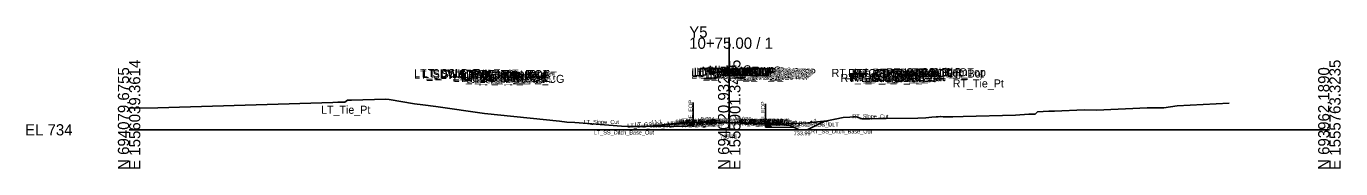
# Model space of a CAD drawing. Extents: x -26 to 4229, y -10 to 9523.
# Drawn here: x -25.7 to 302.8, y 990.3 to 1025.8 of the extents above; entities that cross this region are included whole.
import ezdxf

# ---------------------------------------------------------------- set-up
doc = ezdxf.new("R2010")
doc.units = 0
for name, color, linetype in [('Default', 7, 'Continuous'), ('Exist CMT Pavement', 7, 'Continuous'), ('Exist Cross Section Cell', 7, 'Continuous'), ('Exist XS Center Line Elevation Label', 7, 'Continuous'), ('Exist XS Ground Line', 7, 'Continuous'), ('Prop CMT Pvmt Course 1', 7, 'Continuous'), ('Prop CMT Pvmt Course 1 Wedge', 7, 'Continuous'), ('Prop CMT Pvmt Course 2', 7, 'Continuous'), ('Prop CMT Pvmt Course 2 Wedge', 7, 'Continuous'), ('Prop CMT Pvmt Course 3', 7, 'Continuous'), ('Prop CMT Pvmt Surface', 7, 'Continuous'), ('Prop CMT Pvmt Surface Shoulder', 7, 'Continuous'), ('Prop CMT Pvmt Wedge Surface 1', 7, 'Continuous'), ('Prop CMT Pvmt Wedge Surface 2', 7, 'Continuous'), ('Prop CMT Pvmt Wedge Surface 3', 7, 'Continuous'), ('Prop CMT Shld Paved Course 1', 7, 'Continuous'), ('Prop CMT Shld Paved Course 2', 7, 'Continuous'), ('Prop CMT Shld Paved Course 3', 7, 'Continuous'), ('Prop CMT Slope Grass', 7, 'Continuous'), ('Prop CMT Subgrade Earthwork', 7, 'Continuous'), ('Prop XS Earthwork Shape', 7, 'Continuous'), ('Prop XS Label Text', 7, 'Continuous'), ('Prop XSC Text', 7, 'Continuous'), ('Scratch_Level_1', 7, 'Continuous'), ('Scratch_Level_2', 7, 'Continuous')]:
    doc.layers.add(name, color=color, linetype=linetype)

msp = doc.modelspace()

# ---------------------------------------------------------------- linework, layer by layer
at = {"layer": 'Exist CMT Pavement'}
for p, q in [((142.88, 1001.8), (140.95, 1001.81)), ((157.26, 1001.51), (159.05, 1001.45))]:
    msp.add_line(p, q, dxfattribs=at)
for points in [[(142.88, 1001.8), (150, 1001.75)], [(150, 1001.75), (150.52, 1001.75), (152.93, 1001.68), (157.26, 1001.51)]]:
    msp.add_lwpolyline(points, dxfattribs=at)
at = {"layer": 'Exist Cross Section Cell'}
for p, q in [((150, 1000), (150, 1023.01)), ((0, 1000), (150, 1000)), ((150, 1000), (300, 1000))]:
    msp.add_line(p, q, dxfattribs=at)
at = {"layer": 'Exist XS Ground Line'}
msp.add_lwpolyline([(0, 1005.37), (7.19, 1005.5), (15.32, 1005.71), (50.91, 1006.82), (52.21, 1006.88), (53.27, 1006.87), (53.89, 1006.87), (54.63, 1007.36), (55.56, 1007.37), (64.15, 1007.67), (64.97, 1007.55), (71.36, 1006.51), (73.41, 1006.21), (76.71, 1005.81), (88.81, 1004.07), (107.54, 1002.15), (109.43, 1001.91), (111.39, 1001.86), (123.06, 1000.94), (124.74, 1000.82), (128.94, 1000.82), (129.37, 1000.87), (130.48, 1000.92), (136.24, 1001.61), (140.95, 1001.81), (142.85, 1001.8), (150, 1001.75), (150.52, 1001.75), (152.93, 1001.68), (159.05, 1001.45), (160.86, 1001.29), (162.67, 1001.37), (169.64, 1001.72), (174.39, 1002.24), (176.48, 1002.66), (178.44, 1003.05), (181.83, 1003.2), (182.72, 1002.88), (183.19, 1002.7), (185.16, 1002.74), (187.29, 1002.78), (189.2, 1002.8), (197.14, 1002.92), (199.18, 1003.02), (200.61, 1003.15), (201.69, 1003.21), (202.16, 1003.21), (202.88, 1003.33), (203.48, 1003.21), (204.23, 1003.21), (205.37, 1003.23), (205.88, 1003.24), (208.45, 1003.32), (221.55, 1003.64), (224.87, 1003.91), (225.22, 1003.9), (226.48, 1003.93), (227.02, 1004.46), (229.9, 1004.64), (231.31, 1004.66), (238.69, 1005.02), (241.78, 1004.91), (254.44, 1005.46), (258.66, 1005.52), (261.94, 1005.95), (274.95, 1006.62)], dxfattribs=at)
at = {"layer": 'Prop CMT Pvmt Course 1'}
for points in [[(150, 1001.8), (140.88, 1001.84)], [(140.88, 1001.84), (140.88, 1001.59)], [(140.88, 1001.59), (140.95, 1001.59)], [(140.95, 1001.59), (140.95, 1001.71)], [(150, 1001.8), (159.26, 1001.56)], [(159.05, 1001.32), (159.05, 1001.44)], [(159.26, 1001.31), (159.05, 1001.32)], [(159.26, 1001.56), (159.26, 1001.31)]]:
    msp.add_lwpolyline(points, dxfattribs=at)
at = {"layer": 'Prop CMT Pvmt Course 1 Wedge'}
msp.add_lwpolyline([(159.05, 1001.44), (159.05, 1001.32)], dxfattribs=at)
at = {"layer": 'Prop CMT Pvmt Course 2'}
for points in [[(140.95, 1001.59), (140.88, 1001.59)], [(140.88, 1001.59), (140.88, 1001.34)], [(140.88, 1001.34), (140.95, 1001.34)], [(140.95, 1001.34), (140.95, 1001.59)], [(159.05, 1001.07), (159.05, 1001.32)], [(159.05, 1001.32), (159.26, 1001.31)], [(159.05, 1001.07), (159.26, 1001.06)], [(159.26, 1001.31), (159.26, 1001.06)]]:
    msp.add_lwpolyline(points, dxfattribs=at)
at = {"layer": 'Prop CMT Pvmt Course 2 Wedge'}
for points in [[(157.26, 1001.51), (154.89, 1001.6)], [(159.05, 1001.32), (159.05, 1001.2)]]:
    msp.add_lwpolyline(points, dxfattribs=at)
at = {"layer": 'Prop CMT Pvmt Course 3'}
for points in [[(140.95, 1001.34), (140.88, 1001.34)], [(140.88, 1001.34), (140.88, 1000.96)], [(140.88, 1000.96), (140.95, 1000.96)], [(140.95, 1000.96), (140.95, 1001.34)], [(159.05, 1001.07), (159.26, 1001.06)], [(159.05, 1000.69), (159.05, 1001.07)], [(159.26, 1000.69), (159.05, 1000.69)], [(159.26, 1001.06), (159.26, 1000.69)]]:
    msp.add_lwpolyline(points, dxfattribs=at)
at = {"layer": 'Prop CMT Pvmt Surface'}
for points in [[(150, 1001.8), (140.88, 1001.84)], [(150, 1001.8), (159.26, 1001.56)]]:
    msp.add_lwpolyline(points, dxfattribs=at)
at = {"layer": 'Prop CMT Pvmt Surface Shoulder'}
for points in [[(140.88, 1001.84), (140.88, 1001.84)], [(159.26, 1001.56), (159.26, 1001.56)]]:
    msp.add_lwpolyline(points, dxfattribs=at)
at = {"layer": 'Prop CMT Pvmt Wedge Surface 1'}
for points in [[(140.88, 1001.59), (140.88, 1001.84)], [(140.95, 1001.59), (140.88, 1001.59)], [(140.95, 1001.71), (140.95, 1001.59)], [(159.05, 1001.44), (159.05, 1001.32)], [(159.05, 1001.32), (159.26, 1001.31)], [(159.26, 1001.31), (159.26, 1001.56)]]:
    msp.add_lwpolyline(points, dxfattribs=at)
at = {"layer": 'Prop CMT Pvmt Wedge Surface 2'}
for points in [[(140.88, 1001.59), (140.88, 1001.84)], [(140.95, 1001.59), (140.88, 1001.59)], [(159.05, 1001.32), (159.26, 1001.31)], [(159.26, 1001.31), (159.26, 1001.56)]]:
    msp.add_lwpolyline(points, dxfattribs=at)
at = {"layer": 'Prop CMT Pvmt Wedge Surface 3'}
for points in [[(140.88, 1001.34), (140.88, 1001.84)], [(140.95, 1001.34), (140.88, 1001.34)], [(159.05, 1001.07), (159.26, 1001.06)], [(159.26, 1001.06), (159.26, 1001.56)]]:
    msp.add_lwpolyline(points, dxfattribs=at)
at = {"layer": 'Prop CMT Shld Paved Course 1'}
for points in [[(140.88, 1001.84), (140.63, 1001.58)], [(140.63, 1001.58), (140.88, 1001.59)], [(140.88, 1001.84), (140.88, 1001.84)], [(140.88, 1001.59), (140.88, 1001.84)], [(159.26, 1001.56), (159.26, 1001.56)], [(159.26, 1001.56), (159.52, 1001.31)], [(159.26, 1001.31), (159.26, 1001.56)], [(159.52, 1001.31), (159.26, 1001.31)]]:
    msp.add_lwpolyline(points, dxfattribs=at)
at = {"layer": 'Prop CMT Shld Paved Course 2'}
for points in [[(140.88, 1001.59), (140.63, 1001.58), (140.37, 1001.33)], [(140.37, 1001.33), (140.88, 1001.34)], [(140.88, 1001.34), (140.88, 1001.59)], [(159.26, 1001.31), (159.52, 1001.31), (159.77, 1001.05)], [(159.26, 1001.06), (159.26, 1001.31)], [(159.77, 1001.05), (159.26, 1001.06)]]:
    msp.add_lwpolyline(points, dxfattribs=at)
at = {"layer": 'Prop CMT Shld Paved Course 3'}
for points in [[(140.88, 1001.34), (140.37, 1001.33), (139.87, 1001.32), (139.49, 1000.94)], [(139.49, 1000.94), (140.88, 1000.96)], [(140.88, 1000.96), (140.88, 1001.34)], [(159.26, 1001.06), (159.77, 1001.05), (160.27, 1001.04), (160.65, 1000.66)], [(159.26, 1000.69), (159.26, 1001.06)], [(160.65, 1000.66), (159.26, 1000.69)]]:
    msp.add_lwpolyline(points, dxfattribs=at)
at = {"layer": 'Prop CMT Slope Grass'}
for p, q in [((173.82, 1002.18), (169.45, 999.99)), ((165.26, 1001.08), (167.45, 999.99)), ((167.45, 999.99), (169.45, 999.99))]:
    msp.add_line(p, q, dxfattribs=at)
for points in [[(140.88, 1001.84), (134.88, 1001.36), (128.94, 1000.82)], [(159.26, 1001.56), (165.26, 1001.08)]]:
    msp.add_lwpolyline(points, dxfattribs=at)
at = {"layer": 'Prop CMT Subgrade Earthwork'}
for points in [[(139.49, 1000.94), (128.94, 1000.82)], [(140.88, 1000.96), (139.49, 1000.94)], [(140.95, 1000.96), (140.88, 1000.96)], [(140.95, 1000.96), (140.95, 1001.81)], [(159.05, 1000.69), (159.05, 1001.45)], [(159.05, 1000.69), (159.26, 1000.69)], [(159.26, 1000.69), (160.65, 1000.66)], [(160.65, 1000.66), (166.33, 1000.55)]]:
    msp.add_lwpolyline(points, dxfattribs=at)
at = {"layer": 'Prop XS Earthwork Shape'}
for points in [[(162, 1001.34), (162.67, 1001.37), (169.64, 1001.72), (173.82, 1002.18), (169.45, 999.99), (167.45, 999.99), (166.33, 1000.55), (165.26, 1001.08)], [(129.66, 1000.88), (130.48, 1000.92), (131.74, 1001.07), (134.88, 1001.36), (140.07, 1001.78), (140.95, 1001.81), (140.95, 1000.96), (140.88, 1000.96), (139.49, 1000.94), (128.94, 1000.82)], [(129.66, 1000.88), (128.94, 1000.82), (129.37, 1000.87)], [(131.74, 1001.07), (136.24, 1001.61), (140.07, 1001.78), (134.88, 1001.36)], [(140.95, 1001.81), (142.85, 1001.8), (150, 1001.75), (142.88, 1001.8)], [(157.26, 1001.51), (159.05, 1001.45), (152.93, 1001.68)], [(159.05, 1000.69), (159.05, 1001.45), (160.86, 1001.29), (162, 1001.34), (165.26, 1001.08), (166.33, 1000.55), (160.65, 1000.66), (159.26, 1000.69)]]:
    msp.add_lwpolyline(points, close=True, dxfattribs=at)
at = {"layer": 'Prop XS Label Text'}
for p, q in [((140.95, 1006.81), (140.95, 1001.81)), ((159.05, 1006.45), (159.05, 1001.45))]:
    msp.add_line(p, q, dxfattribs=at)
at = {"layer": 'Scratch_Level_2'}
msp.add_line((128.94, 1000.82), (134.88, 1001.36), dxfattribs=at)

# ---------------------------------------------------------------- texts
at = {"layer": 'Default'}
for s, height, p in [('LT_CSLP_Pnt', 2, (73.17, 1013.15)), ('LT_PV2_OEEOP', 2, (140.56, 1013.36)), ('LT_PV1_OEEOP', 2, (141.12, 1013.48)), ('LT_PV2_IEEOP', 2, (141.2, 1013.36)), ('LT_PV1_IEEOP', 2, (141.77, 1013.48)), ('LT_PV2_PGL1', 2, (142.13, 1013.36)), ('LT_PV2_PGL', 2, (142.46, 1013.36)), ('LT_PV1_PGL', 2, (143.03, 1013.61)), ('MI_Face In', 2, (143.15, 1013.77)), ('MI_Bot In', 2, (144.13, 1013.61)), ('MI_Top In', 2, (144.86, 1014.02)), ('MI_Crown', 2, (149.07, 1014.1)), ('RT_PV1_OEEOP', 2, (150.58, 1013.24)), ('MI_Face Out', 2, (151.01, 1013.53)), ('MI_Top Out', 2, (151.22, 1013.78)), ('RT_PV1_IEEOP', 2, (151.22, 1013.24)), ('MI_Bot Out', 2, (152.01, 1013.37)), ('RT_PV1_PGL', 2, (152.48, 1013.37)), ('RT_Sub_Trench_Out_DLT', 2, (175.59, 1013.19)), ('RT_CG_Top_Face', 2, (179.71, 1013.15)), ('RT_CG_Top_BOC', 2, (181.24, 1013.15)), ('RT_SDWK_In_Top', 2, (185.81, 1013.26)), ('RT_SDWK_Out_Top', 2, (189.19, 1013.36)), ('RT_Shld_O', 2, (195.54, 1013.35)), ('CSLP_Pnt', 2, (197.87, 1013.39)), ('LT_SDWK_Out_Top', 2, (71.24, 1013.12)), ('LT_SDWK_Out_Bot', 2, (71.27, 1012.79)), ('LT_Sub_Trench_Out_DLT', 2, (73.49, 1012.95)), ('LT_SDWK_In_Top', 2, (77.86, 1013.02)), ('LT_SDWK_In_Bot', 2, (77.89, 1012.69)), ('LT_CG1_Shelf_Out', 2, (81.05, 1011.89)), ('LT_CG_Top_Face', 2, (82.76, 1012.91)), ('LT_CG_Top_BOC', 2, (83.28, 1012.91)), ('LT_CG_Bot_BOC', 2, (83.31, 1011.9)), ('LT_CG_Top_Gut', 2, (83.74, 1012.41)), ('LT_Sub_OEOP', 2, (84.36, 1011.63)), ('LT_Sub_OEOT_CG', 2, (84.87, 1011.7)), ('LT_CG_Bot_IE', 2, (87.41, 1011.95)), ('LT_Sub_OEOT', 2, (87.58, 1011.66)), ('LT_PV2_OEOT', 2, (87.67, 1012.28)), ('LT_PV3_OEOT', 2, (87.67, 1012.03)), ('LT_PV1_OEOT', 2, (88.24, 1012.53)), ('LT_Sub_OEEOP', 2, (140.46, 1012.73)), ('LT_PV3_OEEOP', 2, (140.56, 1013.11)), ('LT_PV3_PGL1', 2, (142.13, 1013.11)), ('LT_PV4_PGL', 2, (142.46, 1012.73)), ('RT_Sub_OEEOP', 2, (149.92, 1012.49)), ('RT_PV2_OEEOP', 2, (150.01, 1013.12)), ('RT_PV3_OEEOP', 2, (150.01, 1012.87)), ('RT_PV2_IEEOP', 2, (150.66, 1013.12)), ('RT_PV2_PGL1', 2, (151.58, 1013.12)), ('RT_PV3_PGL1', 2, (151.58, 1012.87)), ('RT_PV2_PGL', 2, (151.92, 1013.12)), ('RT_PV4_PGL', 2, (151.92, 1012.49)), ('RT_Sub_OEOT_CG', 2, (177.82, 1011.94)), ('RT_CG1_Shelf_Out', 2, (180, 1012.13)), ('RT_CG_Bot_IE', 2, (180.37, 1012.19)), ('RT_Sub_OEOT', 2, (180.53, 1011.9)), ('RT_PV2_OEOT', 2, (180.63, 1012.52)), ('RT_PV3_OEOT', 2, (180.63, 1012.27)), ('RT_CG_Top_Gut', 2, (180.69, 1012.65)), ('RT_PV1_OEOT', 2, (181.19, 1012.77)), ('RT_CG_Bot_BOC', 2, (181.27, 1012.14)), ('RT_Sub_OEOP', 2, (183.82, 1011.87)), ('RT_SDWK_In_Bot', 2, (185.84, 1012.93)), ('RT_SDWK_Out_Bot', 2, (189.22, 1013.03)), ('RT_Tie_Pt', 2, (205.86, 1010.57)), ('LT_Tie_Pt', 2, (47.97, 1004)), ('-', 0.0001, (0, 1000)), ('-', 0.0001, (0, 1000)), ('-', 0.0001, (0, 1000)), ('-', 0.0001, (0, 1000)), ('-', 0.0001, (0, 1000)), ('-', 0.0001, (0, 1000)), ('-', 0.0001, (0, 1000)), ('-', 0.0001, (0, 1000)), ('-', 0.0001, (0, 1000)), ('-', 0.0001, (0, 1000))]:
    msp.add_text(s, height=height, dxfattribs=at).set_placement(p)
at = {"layer": 'Exist Cross Section Cell'}
for s, p in [('Y5', (140, 1023.01)), ('10+75.00 / 1', (140, 1020.21)), ('EL 734', (-26, 998.6))]:
    msp.add_text(s, height=2.8, dxfattribs=at).set_placement(p)
for s, p in [('N 694079.6755', (0, 990)), ('E 1556039.3614', (2.8, 990)), ('N 694020.9323', (150, 990)), ('E 1555901.3425', (152.8, 990)), ('N 693962.1890', (300, 990)), ('E 1555763.3235', (302.8, 990))]:
    msp.add_text(s, height=2.8, rotation=90, dxfattribs=at).set_placement(p)
at = {"layer": 'Exist XS Center Line Elevation Label'}
msp.add_text('735.75', height=1, dxfattribs=at).set_placement((147.73, 997.75))
at = {"layer": 'Prop XS Label Text'}
for p in [(140.85, 1002.83), (158.95, 1002.46)]:
    msp.add_text('E. EOP', height=1, rotation=90, dxfattribs=at).set_placement(p)
at = {"layer": 'Prop XSC Text'}
for s, rotation, p in [('11:1', 5.2293, (130.58, 1001.33)), ('0.004', 359.7708, (142.86, 1002.22)), ('0.026', 358.5106, (152.05, 1002.27)), ('2:1', 333.4349, (165.91, 1001.49)), ('2:1', 26.5651, (170.51, 1001.14))]:
    msp.add_text(s, height=1, rotation=rotation, dxfattribs=at).set_placement(p)
msp.add_text('733.99', height=1, dxfattribs=at).set_placement((166.11, 998.63))
at = {"layer": 'Scratch_Level_1'}
for s, p in [('LT_Slope_Cut', (113.6, 1001.47)), ('LT_PS3_Shelf_Out', (134.53, 1001.11)), ('LT_PS3_OEOP', (136.16, 1001.12)), ('LT_PS2_OEOP', (136.41, 1001.37)), ('LT_PV2_OEOT', (136.63, 1001.38)), ('LT_PV3_OEOT', (136.63, 1001.13)), ('LT_PV1_OEOT', (136.75, 1001.63)), ('LT_PS1_OEOP', (136.79, 1001.63)), ('LT_PV_OEEOP_EG', (137.48, 1001.81)), ('LT_Sub Tie Out', (138.04, 1001.81)), ('LT_PV2_OEEOP', (138.27, 1001.42)), ('LT_PV3_OEEOP', (138.27, 1001.17)), ('LT_PV1_OEEOP', (138.39, 1001.55)), ('RT_PV_IEEOP_EG', (144.92, 1001.77)), ('LT_PV_IEEOP_EG', (144.98, 1001.77)), ('RT_PV2_IEEOP', (145.71, 1001.56)), ('RT_PV3_IEEOP', (145.71, 1001.31)), ('LT_PV2_IEEOP', (145.77, 1001.56)), ('LT_PV3_IEEOP', (145.77, 1001.31)), ('RT_PV1_IEEOP', (145.83, 1001.69)), ('LT_PV1_IEEOP', (145.89, 1001.69)), ('PV2_PGL', (147.35, 1001.56)), ('PV1_PGL', (147.47, 1001.81)), ('RT_PV_OEEOP_EG', (151.8, 1001.53)), ('RT_Sub Tie Out', (152.36, 1001.52)), ('RT_PV2_OEEOP', (152.59, 1001.64)), ('RT_PV3_OEEOP', (152.59, 1001.39)), ('RT_Sub_OEEOP', (152.62, 1001.01)), ('RT_PV1_OEEOP', (152.71, 1001.76)), ('RT_Sub_Trench_Out', (154.7, 1001.01)), ('RT_PS3_Shelf_Out', (154.87, 1001.39)), ('RT_PV2_OEOT', (154.95, 1001.66)), ('RT_PV3_OEOT', (154.95, 1001.41)), ('RT_Sub_OEOT', (154.97, 1001.03)), ('RT_PV1_OEOT', (155.07, 1001.9)), ('RT_PS1_OEOP', (155.11, 1001.9)), ('RT_PS2_OEOP', (155.24, 1001.65)), ('RT_PS3_OEOP', (155.5, 1001.39)), ('RT_GS_OS_CTL', (164.66, 1001.11)), ('RT_Slope_Cut', (180.77, 1002.88)), ('LT_SS_Ditch_Base_Out', (116.14, 998.84)), ('LT_Sub_OSS_DLT', (124.53, 1000.53)), ('LT_GS_OS_CTL', (126.34, 1000.83)), ('LT_Sub_Trench_Out', (133.6, 1000.73)), ('LT_Sub_OEOT', (136.65, 1000.75)), ('LT_Sub_OEEOP', (138.3, 1000.8)), ('RT_Sub_OSS_DLT', (165.24, 1000.81)), ('RT_SS_Ditch_Base_Out', (170.46, 999.11))]:
    msp.add_text(s, height=1, rotation=359.8763, dxfattribs=at).set_placement(p)

doc.saveas('drawing.dxf')
